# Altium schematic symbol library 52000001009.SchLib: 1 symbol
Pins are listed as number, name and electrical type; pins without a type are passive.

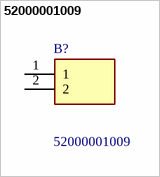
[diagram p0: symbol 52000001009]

## 52000001009
designator B?
Littelfuse Phosphor Bronze PCB Mount Fuse Clip for 5 x 20mm Cartridge Fuse; Geometry.Height: 8mm
footprint 52000001009
pins: 1, 2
